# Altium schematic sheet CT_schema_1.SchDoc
size 662 x 518 mm
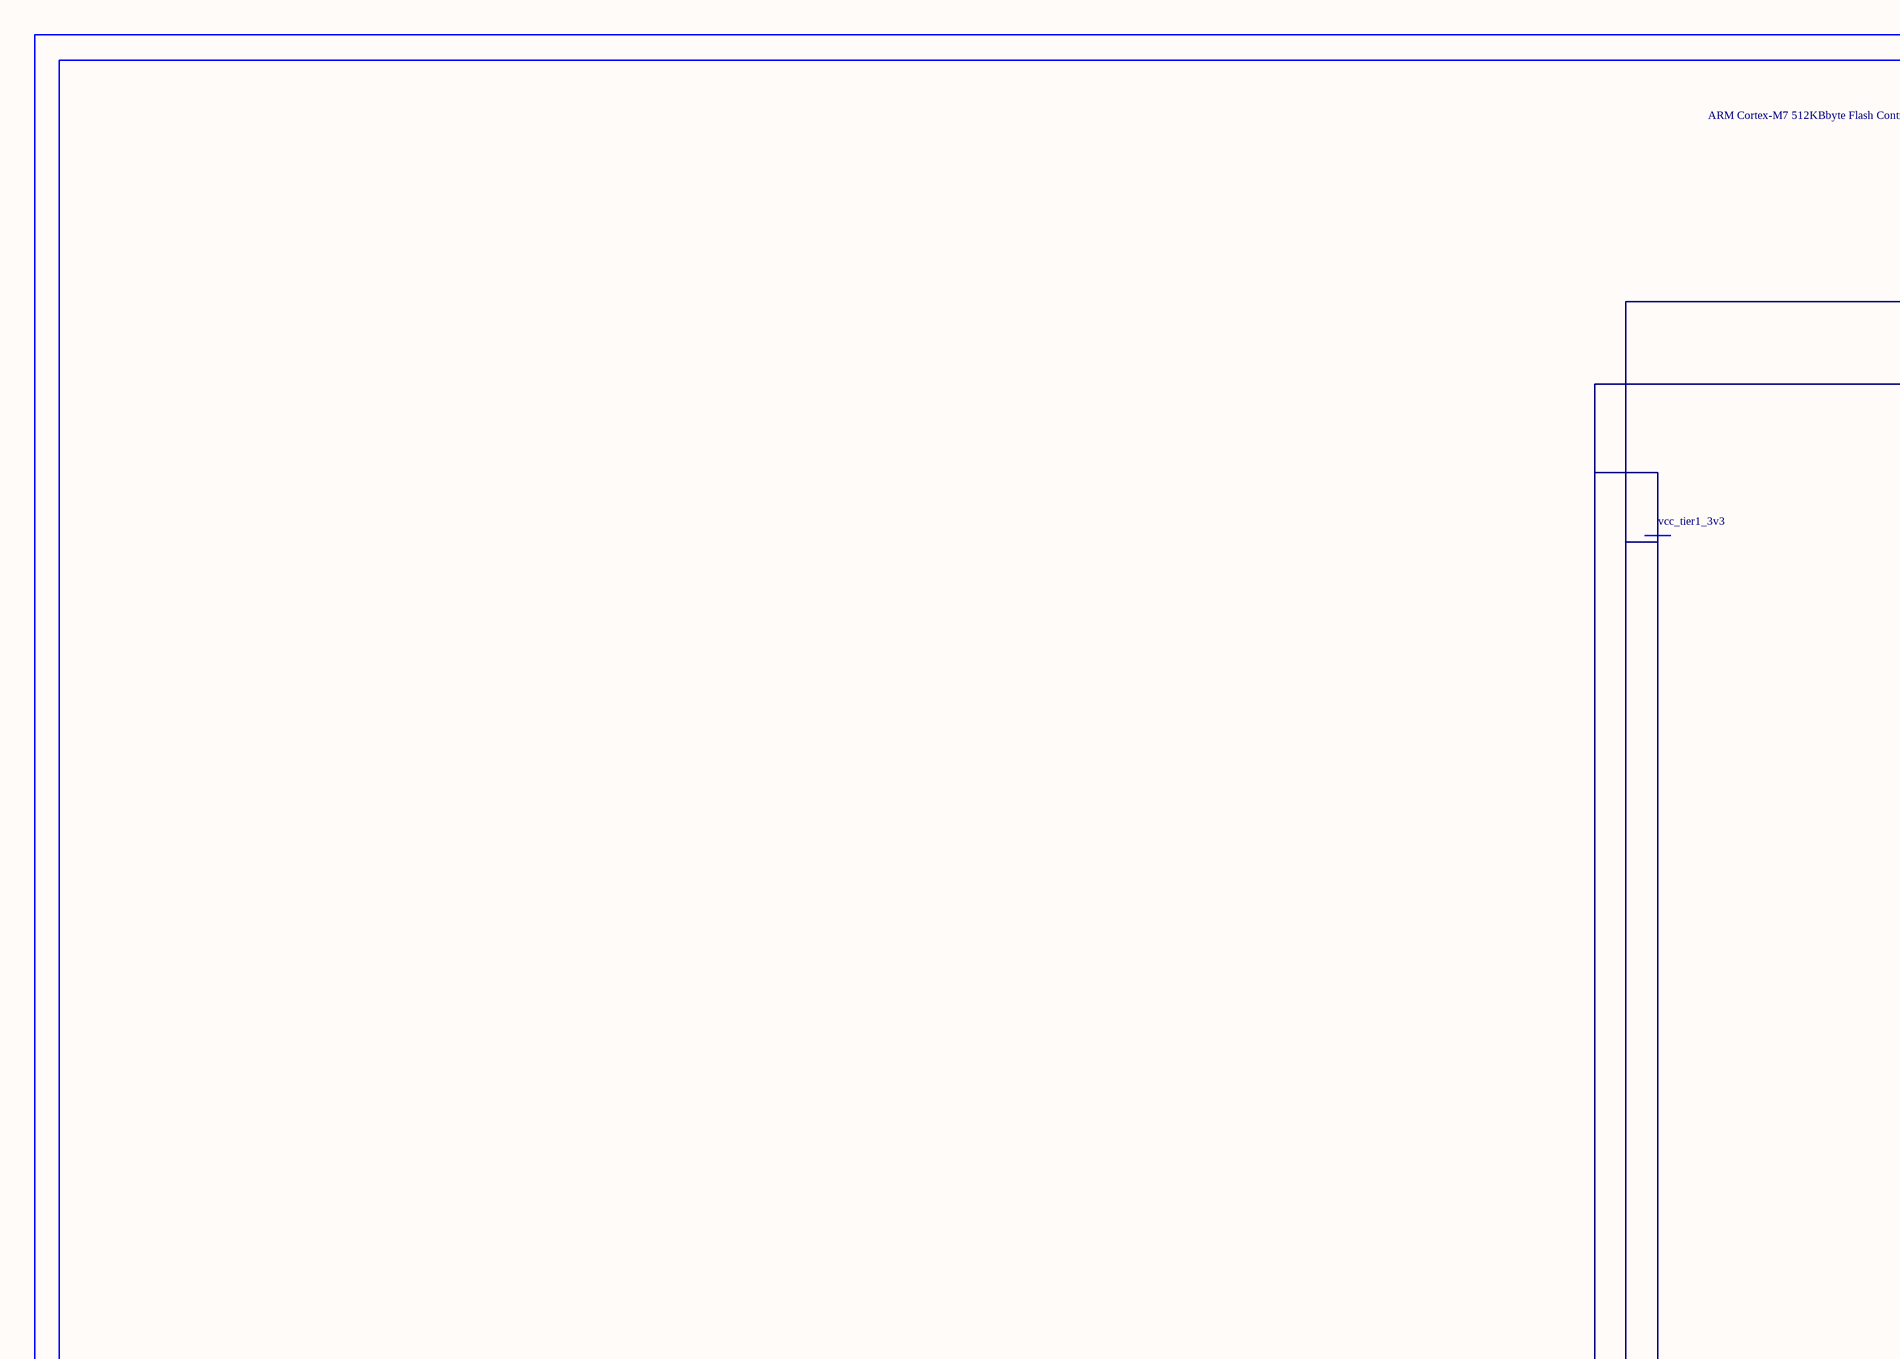
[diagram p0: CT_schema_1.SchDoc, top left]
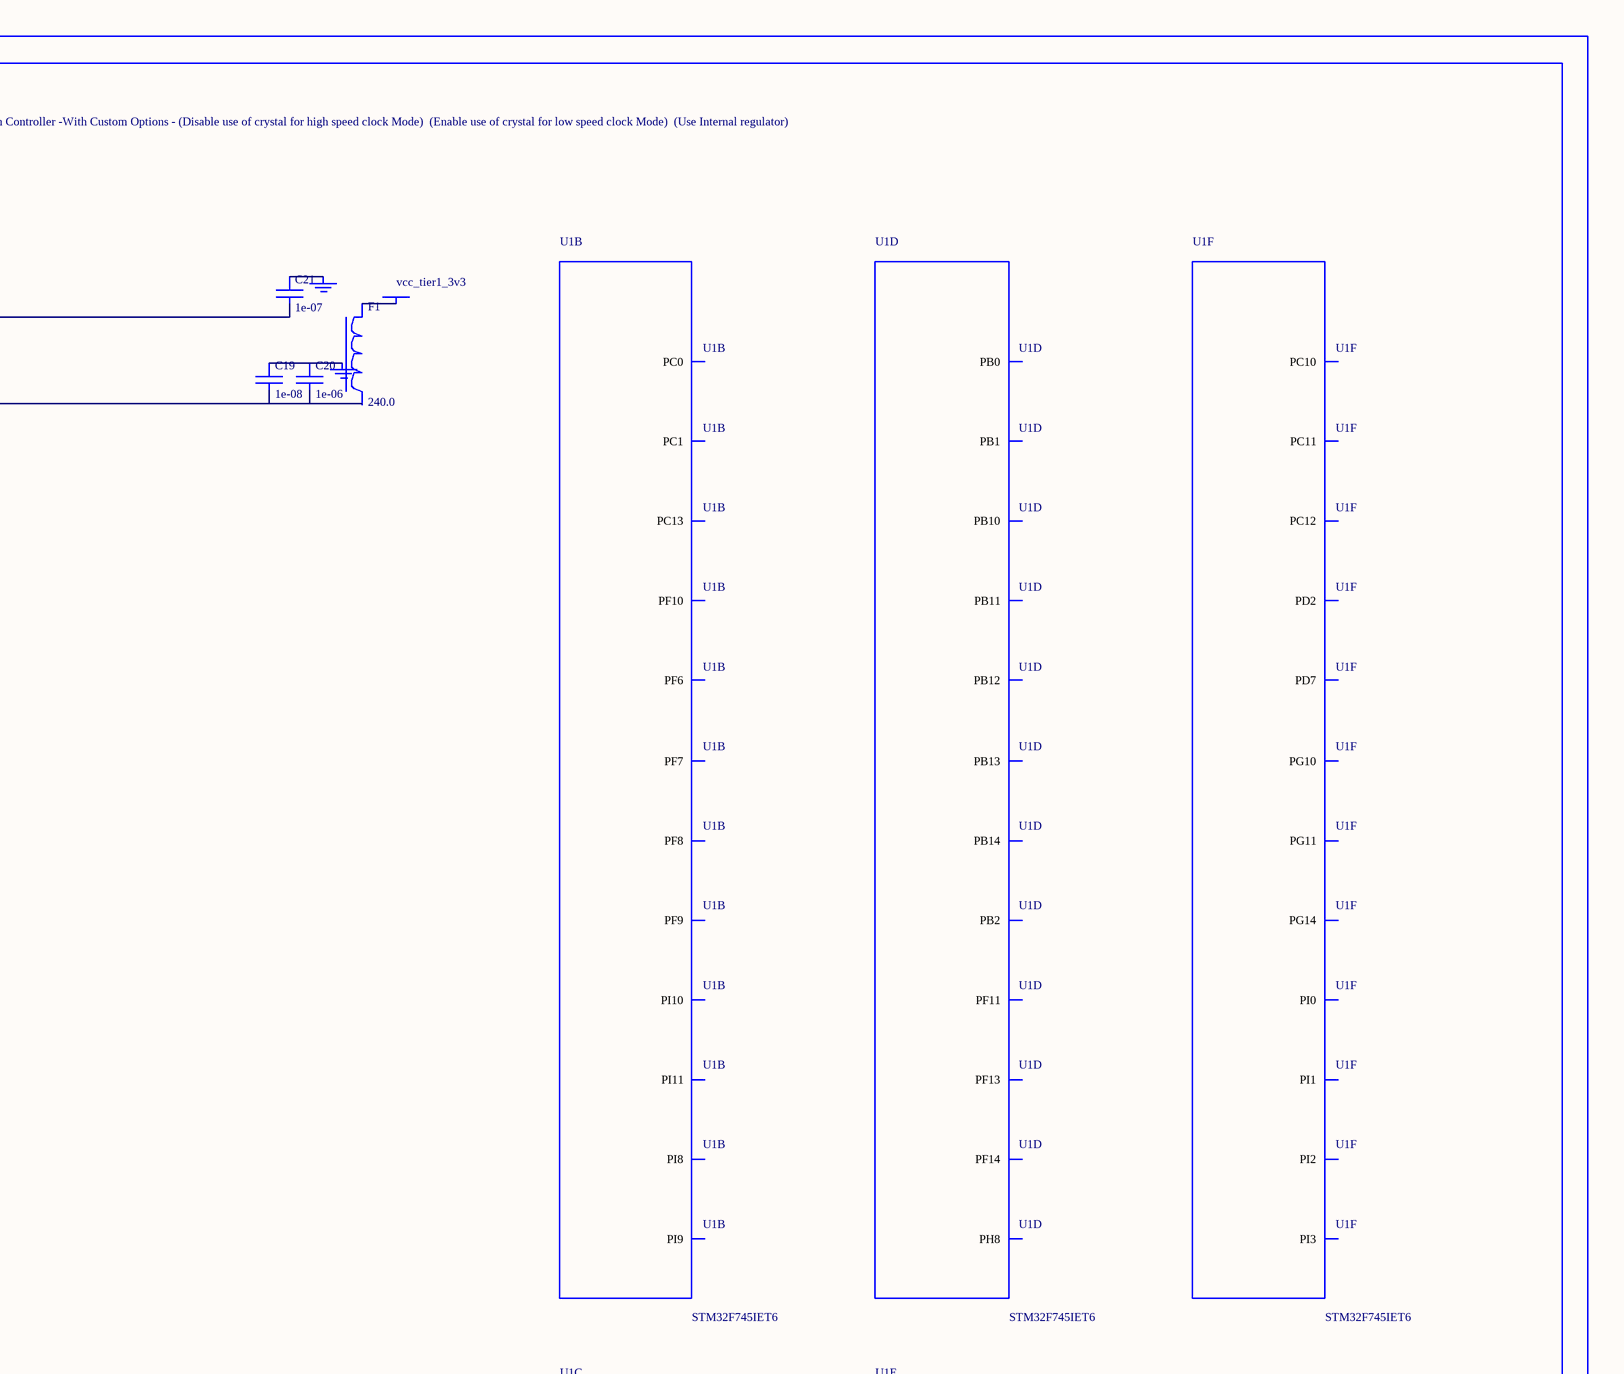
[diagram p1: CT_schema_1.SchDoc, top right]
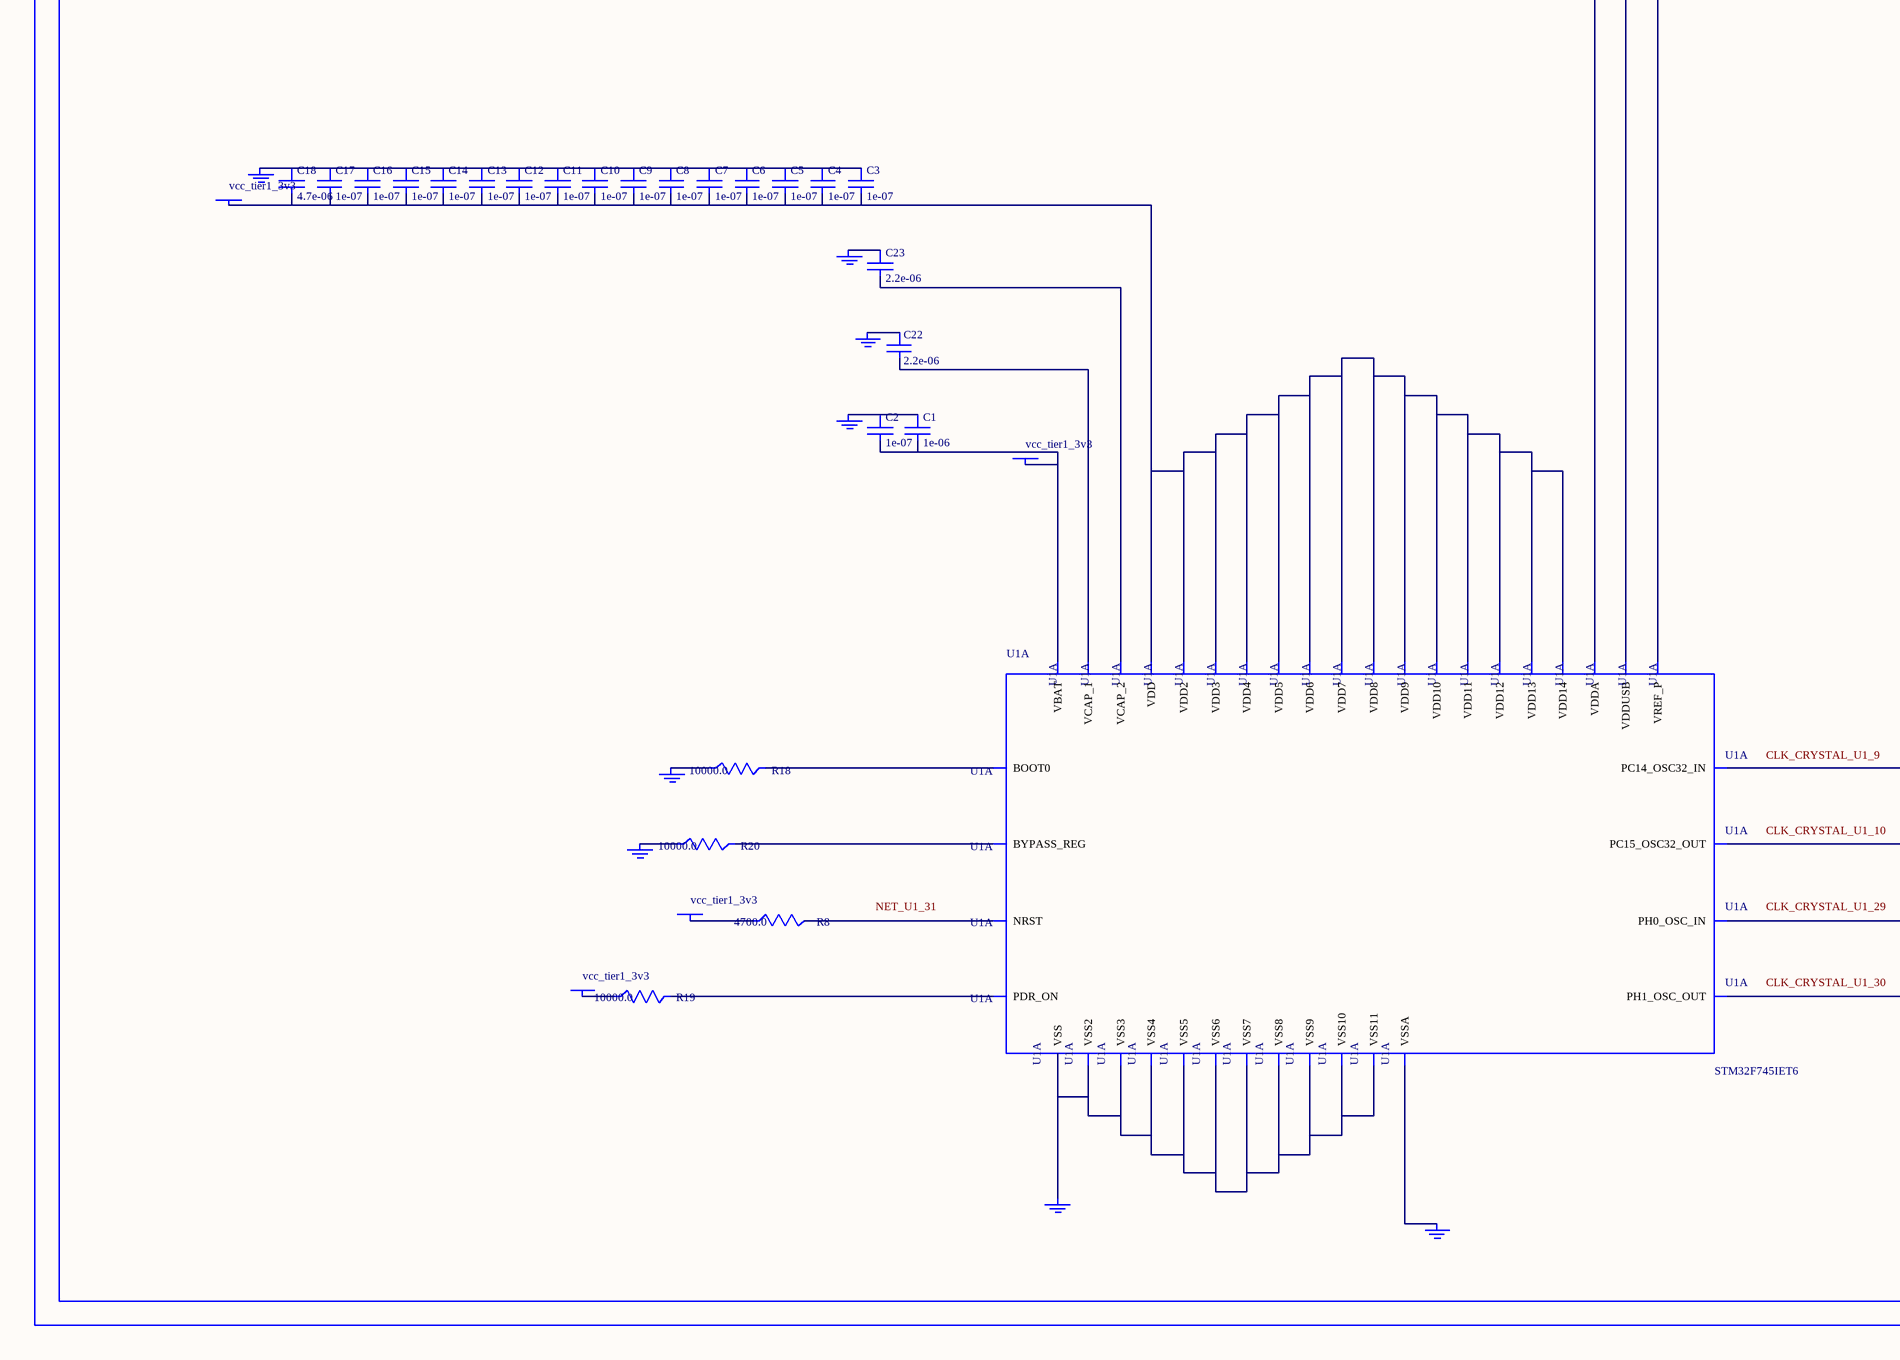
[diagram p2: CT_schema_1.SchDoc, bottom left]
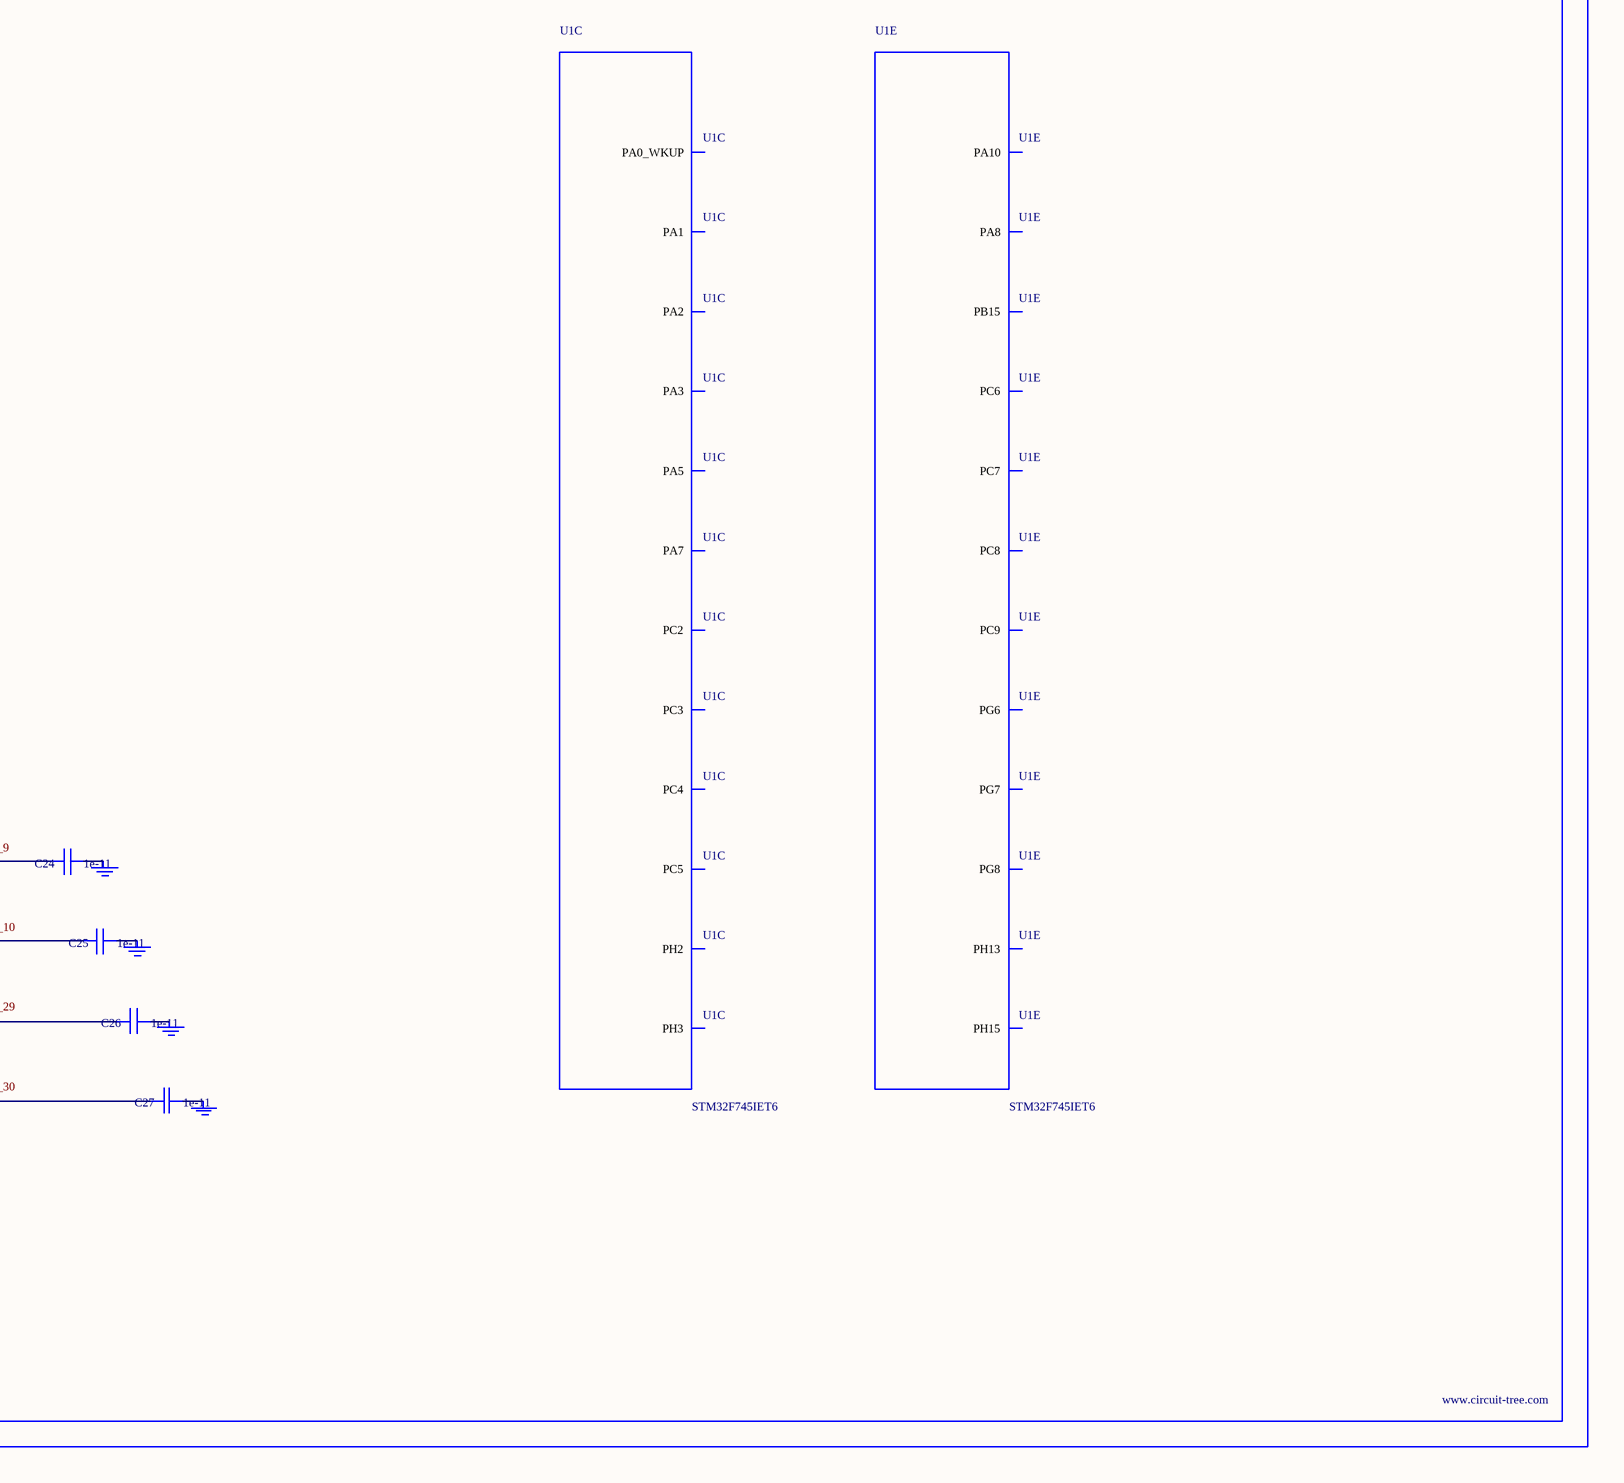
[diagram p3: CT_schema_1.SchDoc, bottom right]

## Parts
BORDER0  (no value)
C1  1e-06  [C0603]
C2  1e-07  [C0603]
C3  1e-07  [C0603]
C4  1e-07  [C0603]
C5  1e-07  [C0603]
C6  1e-07  [C0603]
C7  1e-07  [C0603]
C8  1e-07  [C0603]
C9  1e-07  [C0603]
C10  1e-07  [C0603]
C11  1e-07  [C0603]
C12  1e-07  [C0603]
C13  1e-07  [C0603]
C14  1e-07  [C0603]
C15  1e-07  [C0603]
C16  1e-07  [C0603]
C17  1e-07  [C0603]
C18  4.7e-06  [C0603]
C19  1e-08  [C0603]
C20  1e-06  [C0603]
C21  1e-07  [C0603]
C22  2.2e-06  [C0603]
C23  2.2e-06  [C0603]
C24  1e-11  [C0402]
C25  1e-11  [C0402]
C26  1e-11  [C0402]
C27  1e-11  [C0402]
F1  240.0  [L0603]
GND_INSTANCE_0_0  (no value)
GND_INSTANCE_0_1  (no value)
GND_INSTANCE_0_2  (no value)
GND_INSTANCE_0_3  (no value)
GND_INSTANCE_0_4  (no value)
GND_INSTANCE_0_5  (no value)
GND_INSTANCE_0_6  (no value)
GND_INSTANCE_0_7  (no value)
GND_INSTANCE_0_8  (no value)
GND_INSTANCE_0_9  (no value)
GND_INSTANCE_0_10  (no value)
GND_INSTANCE_0_11  (no value)
GND_INSTANCE_0_12  (no value)
GND_INSTANCE_0_13  (no value)
POWER_INSTANCE_0_0  vcc_tier1_3v3
POWER_INSTANCE_0_1  vcc_tier1_3v3
POWER_INSTANCE_0_2  vcc_tier1_3v3
POWER_INSTANCE_0_3  vcc_tier1_3v3
POWER_INSTANCE_0_4  vcc_tier1_3v3
POWER_INSTANCE_0_5  vcc_tier1_3v3
R8  4700.0  [R0603]
R18  10000.0  [R0603]
R19  10000.0  [R0603]
R20  10000.0  [R0603]
U1  STM32F745IET6  [LQFP176]  (parts A,B,C,D,E,F of 14)

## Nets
NetC1_1: C1.1 C2.1 GND_INSTANCE_0_0.0(GND)
NetC1_2: C1.2 C2.2 POWER_INSTANCE_0_0.0(PWR) U1.6(VBAT)
NetC3_1: C3.1 C4.1 C5.1 C6.1 C7.1 C8.1 C9.1 C10.1 C11.1 C12.1 C13.1 C14.1 C15.1 C16.1 C17.1 C18.1 GND_INSTANCE_0_3.0(GND)
NetC3_2: C3.2 C4.2 C5.2 C6.2 C7.2 C8.2 C9.2 C10.2 C11.2 C12.2 C13.2 C14.2 C15.2 C16.2 C17.2 C18.2 POWER_INSTANCE_0_1.0(PWR) U1.15(VDD) U1.23(VDD2) U1.36(VDD3) U1.49(VDD4) U1.62(VDD5) U1.72(VDD6) U1.82(VDD7) U1.91(VDD8) U1.103(VDD9) U1.127(VDD10) U1.136(VDD11) U1.149(VDD12) U1.159(VDD13) U1.172(VDD14)
NetC19_1: C19.1 C20.1 GND_INSTANCE_0_7.0(GND)
NetC19_2: C19.2 C20.2 C21.2 POWER_INSTANCE_0_3.0(PWR) U1.38(VREF_P) U1.39(VDDA) U1.114(VDDUSB)
NetC21_1: C21.1 GND_INSTANCE_0_10.0(GND)
NetC22_1: C22.1 GND_INSTANCE_0_9.0(GND)
NetC22_2: C22.2 U1.81(VCAP_1)
NetC23_1: C23.1 GND_INSTANCE_0_11.0(GND)
NetC23_2: C23.2 U1.125(VCAP_2)
NetC24_1: C24.1 GND_INSTANCE_0_1.0(GND)
NetC24_2: C24.2 U1.9(PC14_OSC32_IN)
NetC25_1: C25.1 GND_INSTANCE_0_2.0(GND)
NetC25_2: C25.2 U1.10(PC15_OSC32_OUT)
NetC26_1: C26.1 GND_INSTANCE_0_4.0(GND)
NetC26_2: C26.2 U1.29(PH0_OSC_IN)
NetC27_1: C27.1 GND_INSTANCE_0_5.0(GND)
NetC27_2: C27.2 U1.30(PH1_OSC_OUT)
NetF1_1: F1.1 POWER_INSTANCE_0_2.0(PWR)
NetGND_INSTANCE_0_6_0: GND_INSTANCE_0_6.0(GND) U1.37(VSSA)
NetGND_INSTANCE_0_8_0: GND_INSTANCE_0_8.0(GND) R20.1
NetGND_INSTANCE_0_12_0: GND_INSTANCE_0_12.0(GND) R18.1
NetGND_INSTANCE_0_13_0: GND_INSTANCE_0_13.0(GND) U1.14(VSS) U1.22(VSS2) U1.61(VSS3) U1.71(VSS4) U1.90(VSS5) U1.102(VSS6) U1.113(VSS7) U1.126(VSS8) U1.135(VSS9) U1.148(VSS10) U1.158(VSS11)
NetPOWER_INSTANCE_0_4_0: POWER_INSTANCE_0_4.0(PWR) R19.1
NetPOWER_INSTANCE_0_5_0: POWER_INSTANCE_0_5.0(PWR) R8.1
NetR8_2: R8.2 U1.31(NRST)
NetR18_2: R18.2 U1.166(BOOT0)
NetR19_2: R19.2 U1.171(PDR_ON)
NetR20_2: R20.2 U1.48(BYPASS_REG)

Not connected (* = marked no-connect by the designer): F1 2; U1 7(PI8) 8(PC13) 11(PI9) 12(PI10) 13(PI11) 24(PF6) 25(PF7) 26(PF8) 27(PF9) 28(PF10) 32(PC0) 33(PC1) 34(PC2) 35(PC3) 40(PA0_WKUP) 41(PA1) 42(PA2) 43(PH2) 44(PH3) 47(PA3) 51(PA5) 53(PA7) 54(PC4) 55(PC5) 56(PB0) 57(PB1) 58(PB2) 59(PF11) 63(PF13) 64(PF14) 79(PB10) 80(PB11) 85(PH8) 92(PB12) 93(PB13) 94(PB14) 95(PB15) 110(PG6) 111(PG7) 112(PG8) 115(PC6) 116(PC7) 117(PC8) 118(PC9) 119(PA8) 121(PA10) 128(PH13) 130(PH15) 131(PI0) 132(PI1) 133(PI2) 134(PI3) 139(PC10) 140(PC11) 141(PC12) 144(PD2) 151(PD7) 153(PG10) 154(PG11) 157(PG14)

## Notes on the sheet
- Labels drawn without touching a wire or pin: CLK_CRYSTAL_U1_9, CLK_CRYSTAL_U1_10, CLK_CRYSTAL_U1_29, CLK_CRYSTAL_U1_30, NET_U1_31

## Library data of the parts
BORDER0 = BORDER_PAGE0
C1 C20 = C0603C105K3RACTU
C2-C17 C21 = 06035C104K4Z2A
C18 = GRM188R6YA475KE15D
C19 = 06035C103K4Z2A
C22 C23 = C0603C225K8RACTU
C24-C27 = C0402C100K3GACTU
F1 = Z0603C241ASMST
GND_INSTANCE_0_0-GND_INSTANCE_0_13 = GND
POWER_INSTANCE_0_0-POWER_INSTANCE_0_5 = PWR
R8 = RC0603JR-074K7L
R18-R20 = RC0603JR-0710KL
